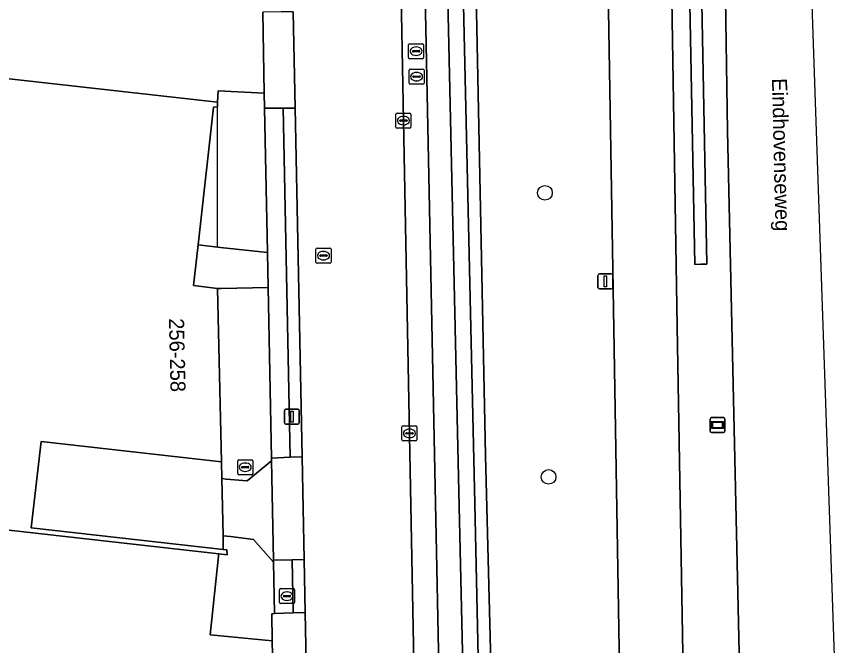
# Model space of a CAD drawing. Extents: x 161385 to 162589, y 388479 to 389756.
# Drawn here: x 162475.1 to 162530.5, y 388850.8 to 388892.6 of the extents above; entities that cross this region are included whole.
import ezdxf

# ---------------------------------------------------------------- set-up
doc = ezdxf.new("R2010")
doc.units = 0
for name, color, linetype in [('IMGEO_Berm_groen', 7, 'Continuous'), ('IMGEO_Boom', 7, 'Continuous'), ('IMGEO_Brandkraan', 7, 'Continuous'), ('IMGEO_Erf', 7, 'Continuous'), ('IMGEO_Fietspad_gesloten', 7, 'Continuous'), ('IMGEO_Groenvoorziening', 7, 'Continuous'), ('IMGEO_Haag', 7, 'Continuous'), ('IMGEO_Kolk', 7, 'Continuous'), ('IMGEO_Lichtmast', 7, 'Continuous'), ('IMGEO_Oever', 7, 'Continuous'), ('IMGEO_Openbare_ruimte_label', 7, 'Continuous'), ('IMGEO_Pand', 7, 'Continuous'), ('IMGEO_Pand_nummerreeks', 7, 'Continuous'), ('IMGEO_Pand_overbouw', 7, 'Continuous'), ('IMGEO_Rijbaan_lokaal_gesloten', 7, 'Continuous'), ('IMGEO_Rijbaan_regionaal_gesloten', 7, 'Continuous'), ('IMGEO_Rioolput', 7, 'Continuous'), ('IMGEO_Voetpad_open', 7, 'Continuous'), ('IMGEO_Waterloop', 7, 'Continuous'), ('IMGEO_Wegwijzer', 7, 'Continuous')]:
    doc.layers.add(name, color=color, linetype=linetype)

msp = doc.modelspace()

# ---------------------------------------------------------------- linework, layer by layer
at = {"layer": 'IMGEO_Berm_groen'}
for points in [[(162515.397, 389079.082), (162515.507, 389081.426), (162514.292, 389081.426), (162514.262, 389079.427), (162515.393, 389057.642), (162516.561, 389022.995), (162519.033, 388871.958), (162521.523, 388727.275)], [(162517.21, 388728.105), (162514.823, 388871.796), (162512.275, 389022.964), (162511.097, 389057.663), (162510.235, 389079.2)], [(162521.311, 388720.501), (162521.33, 388719.939), (162521.52, 388719.331), (162523.238, 388715.161), (162525.385, 388736.547), (162525.398, 388750), (162525.392, 388750.463), (162524.813, 388770.581), (162524.652, 388775.367), (162524.277, 388798.785), (162523.635, 388828.454), (162522.364, 388884.975), (162520.774, 388990.381)], [(162500.546, 388899.883), (162500.817, 388885.662), (162501.627, 388843.777), (162502.076, 388822.868), (162502.515, 388801.899), (162502.522, 388800.855), (162502.53, 388799.811), (162502.501, 388799.311), (162502.302, 388797.58), (162501.949, 388795.874), (162501.444, 388794.206), (162500.793, 388792.59), (162500, 388791.038), (162499.863, 388790.8), (162498.913, 388789.338), (162497.837, 388787.967), (162496.642, 388786.698)], [(162505.585, 388897.306), (162506.277, 388863.384), (162507.703, 388808.23), (162508.502, 388764.034), (162508.507, 388763.596), (162508.048, 388750), (162507.287, 388742.621), (162504.955, 388729.188), (162504.276, 388726.446), (162500, 388712.436), (162499.893, 388712.133), (162499.135, 388710.054), (162493.393, 388696.514), (162489.638, 388688.939), (162485.689, 388681.463), (162483.678, 388677.768)], [(162503.938, 388784.771), (162503.945, 388811.232), (162502.197, 388897.243)]]:
    msp.add_lwpolyline(points, dxfattribs=at)
for points in [[(162521, 388876.114), (162520.6, 388876.106), (162520.2, 388876.098), (162518.628, 388958.294), (162519.028, 388958.302), (162519.428, 388958.31)], [(162493.608, 388886.494), (162492.812, 388886.492), (162493.279, 388863.267), (162494.075, 388863.303)], [(162494.213, 388856.462), (162493.417, 388856.444), (162493.488, 388852.907), (162494.284, 388852.938)]]:
    msp.add_lwpolyline(points, close=True, dxfattribs=at)
at = {"layer": 'IMGEO_Boom'}
for centre in [(162510.232, 388880.857), (162510.475, 388861.96)]:
    msp.add_circle(centre, 0.489, dxfattribs=at)
at = {"layer": 'IMGEO_Brandkraan'}
for p, q in [((162492.571, 388853.599), (162492.571, 388854.451)), ((162492.646, 388854.525), (162493.498, 388854.525)), ((162493.059, 388854.305), (162493.084, 388854.305)), ((162493.572, 388854.451), (162493.572, 388853.599)), ((162492.83, 388854.019), (162492.83, 388854.031)), ((162493.268, 388853.982), (162492.87, 388853.982)), ((162492.873, 388854.068), (162493.271, 388854.068)), ((162493.082, 388853.745), (162493.057, 388853.745)), ((162493.314, 388854.031), (162493.314, 388854.019)), ((162493.498, 388853.525), (162492.646, 388853.525))]:
    msp.add_line(p, q, dxfattribs=at)
for points in [[(162492.571, 388853.599), (162492.571, 388854.451)], [(162492.646, 388854.525), (162493.498, 388854.525)], [(162493.572, 388854.451), (162493.572, 388853.599)], [(162493.498, 388853.525), (162492.646, 388853.525)]]:
    msp.add_lwpolyline(points, dxfattribs=at)
for centre, radius, start, end in [((162492.648, 388854.449), 0.0765, 91.552, 178.448), ((162492.648, 388854.449), 0.0765, 91.552, 178.448), ((162493.496, 388854.449), 0.0765, 1.552, 88.448), ((162493.496, 388854.449), 0.0765, 1.552, 88.448), ((162492.648, 388853.601), 0.0765, 181.552, 268.448), ((162492.648, 388853.601), 0.0765, 181.552, 268.448), ((162492.87, 388854.028), 0.0403, 85.8775, 175.7526), ((162492.867, 388854.018), 0.0366, 178.938, 274.7102), ((162493.271, 388854.025), 0.043, 264.8664, 352.4533), ((162493.275, 388854.03), 0.0386, 1.7309, 96.639), ((162493.496, 388853.601), 0.0765, 271.552, 358.448), ((162493.496, 388853.601), 0.0765, 271.552, 358.448)]:
    msp.add_arc(centre, radius, start, end, dxfattribs=at)
for centre, major_axis, ratio, start_param, end_param in [((162493.058, 388854.025), (-0.387, 0.002), 0.722429, 4.712389, 7.853982), ((162493.083, 388854.025), (-0.39, 0.002), 0.717154, 1.570796, 4.712389)]:
    msp.add_ellipse(centre, major_axis=major_axis, ratio=ratio, start_param=start_param, end_param=end_param, dxfattribs=at)
at = {"layer": 'IMGEO_Erf'}
msp.add_lwpolyline([(162423.214, 388797.141), (162434.552, 388795.859), (162435.263, 388802.18), (162436.753, 388802.017), (162439.735, 388801.682), (162439.879, 388801.637), (162440.168, 388805.317), (162445.286, 388850.441), (162482.306, 388846.26), (162482.466, 388837.077), (162482.487, 388836.004), (162487.823, 388836.098), (162489.492, 388836.131), (162492.433, 388836.158), (162492.098, 388851.061), (162487.953, 388851.459), (162488.523, 388856.678), (162488.541, 388856.845), (162437.609, 388862.581), (162440.94, 388892.207), (162488.443, 388886.892), (162488.497, 388887.644), (162491.565, 388887.495), (162491.458, 388892.887)], dxfattribs=at)
msp.add_lwpolyline([(162488.838, 388857.129), (162488.818, 388858.047), (162488.735, 388861.843), (162488.711, 388862.963), (162476.732, 388864.303), (162476.064, 388858.567)], close=True, dxfattribs=at)
at = {"layer": 'IMGEO_Fietspad_gesloten'}
for points in [[(162519.033, 388871.958), (162516.561, 389022.995), (162515.393, 389057.642), (162514.262, 389079.427), (162514.292, 389081.426), (162514.386, 389087.66), (162514.743, 389099.436), (162509.811, 389099.872), (162509.798, 389099.728), (162509.789, 389099.382), (162509.527, 389088.495), (162510.065, 389081.426), (162510.235, 389079.2), (162511.097, 389057.663), (162512.275, 389022.964), (162514.823, 388871.796), (162517.21, 388728.105)], [(162521.523, 388727.275), (162519.033, 388871.958)]]:
    msp.add_lwpolyline(points, dxfattribs=at)
at = {"layer": 'IMGEO_Groenvoorziening'}
for points in [[(162519.428, 388958.31), (162519.028, 388958.302), (162518.628, 388958.294), (162520.2, 388876.098), (162520.6, 388876.106), (162521, 388876.114)], [(162491.585, 388886.489), (162491.565, 388887.495), (162488.497, 388887.644), (162488.443, 388886.892), (162488.44, 388886.587), (162488.176, 388886.563), (162487.162, 388877.408), (162487.16, 388877.388), (162488.641, 388877.224), (162491.775, 388876.877)], [(162488.711, 388862.963), (162488.735, 388861.843), (162489.024, 388861.816), (162490.432, 388861.686), (162492.049, 388863.021), (162492.045, 388863.211), (162491.821, 388874.558), (162488.7, 388874.497), (162488.46, 388874.492)], [(162489.074, 388857.102), (162489.089, 388856.783), (162488.541, 388856.845), (162488.523, 388856.678), (162487.953, 388851.459), (162492.098, 388851.061), (162492.071, 388852.85), (162492.25, 388852.862), (162492.182, 388856.279), (162490.853, 388857.798), (162489.307, 388857.987), (162489.064, 388858.017), (162488.818, 388858.047), (162488.838, 388857.129)]]:
    msp.add_lwpolyline(points, close=True, dxfattribs=at)
at = {"layer": 'IMGEO_Haag'}
for points in [[(162519.428, 388958.31), (162519.028, 388958.302), (162518.628, 388958.294), (162520.2, 388876.098), (162520.6, 388876.106), (162521, 388876.114)], [(162488.711, 388862.963), (162488.735, 388861.843), (162489.024, 388861.816), (162490.432, 388861.686), (162492.049, 388863.021), (162492.045, 388863.211), (162491.821, 388874.558), (162488.7, 388874.497), (162488.46, 388874.492)]]:
    msp.add_lwpolyline(points, close=True, dxfattribs=at)
at = {"layer": 'IMGEO_Kolk'}
for p, q in [((162500.318, 388885.236), (162500.318, 388886.088)), ((162500.393, 388886.162), (162501.245, 388886.162)), ((162500.806, 388885.942), (162500.831, 388885.942)), ((162501.319, 388886.088), (162501.319, 388885.236)), ((162500.577, 388885.656), (162500.577, 388885.668)), ((162501.015, 388885.619), (162500.617, 388885.619)), ((162500.62, 388885.705), (162501.018, 388885.705)), ((162500.829, 388885.382), (162500.804, 388885.382)), ((162501.061, 388885.668), (162501.061, 388885.656)), ((162501.245, 388885.162), (162500.393, 388885.162)), ((162500.719, 388864.429), (162500.719, 388865.281)), ((162500.794, 388865.355), (162501.646, 388865.355)), ((162501.72, 388865.281), (162501.72, 388864.429)), ((162500.978, 388864.849), (162500.978, 388864.861)), ((162501.416, 388864.812), (162501.018, 388864.812)), ((162501.021, 388864.898), (162501.419, 388864.898)), ((162501.207, 388865.135), (162501.232, 388865.135)), ((162501.462, 388864.861), (162501.462, 388864.849)), ((162501.646, 388864.355), (162500.794, 388864.355)), ((162501.23, 388864.575), (162501.205, 388864.575))]:
    msp.add_line(p, q, dxfattribs=at)
for points in [[(162500.318, 388885.236), (162500.318, 388886.088)], [(162500.393, 388886.162), (162501.245, 388886.162)], [(162501.319, 388886.088), (162501.319, 388885.236)], [(162501.245, 388885.162), (162500.393, 388885.162)], [(162500.719, 388864.429), (162500.719, 388865.281)], [(162500.794, 388865.355), (162501.646, 388865.355)], [(162501.72, 388865.281), (162501.72, 388864.429)], [(162501.646, 388864.355), (162500.794, 388864.355)]]:
    msp.add_lwpolyline(points, dxfattribs=at)
for centre, radius, start, end in [((162500.395, 388886.086), 0.0765, 91.552, 178.448), ((162500.395, 388886.086), 0.0765, 91.552, 178.448), ((162501.243, 388886.086), 0.0765, 1.552, 88.448), ((162501.243, 388886.086), 0.0765, 1.552, 88.448), ((162500.395, 388885.238), 0.0765, 181.552, 268.448), ((162500.395, 388885.238), 0.0765, 181.552, 268.448), ((162500.617, 388885.665), 0.0403, 85.8775, 175.7526), ((162500.614, 388885.655), 0.0366, 178.938, 274.7102), ((162501.018, 388885.662), 0.043, 264.8664, 352.4533), ((162501.022, 388885.667), 0.0386, 1.7309, 96.639), ((162501.243, 388885.238), 0.0765, 271.552, 358.448), ((162501.243, 388885.238), 0.0765, 271.552, 358.448), ((162500.796, 388865.279), 0.0765, 91.552, 178.448), ((162500.796, 388865.279), 0.0765, 91.552, 178.448), ((162501.644, 388865.279), 0.0765, 1.552, 88.448), ((162501.644, 388865.279), 0.0765, 1.552, 88.448), ((162501.018, 388864.858), 0.0403, 85.8775, 175.7526), ((162501.015, 388864.848), 0.0366, 178.938, 274.7102), ((162501.419, 388864.855), 0.043, 264.8664, 352.4533), ((162501.423, 388864.86), 0.0386, 1.7309, 96.639), ((162500.796, 388864.431), 0.0765, 181.552, 268.448), ((162500.796, 388864.431), 0.0765, 181.552, 268.448), ((162501.644, 388864.431), 0.0765, 271.552, 358.448), ((162501.644, 388864.431), 0.0765, 271.552, 358.448)]:
    msp.add_arc(centre, radius, start, end, dxfattribs=at)
for centre, major_axis, ratio, start_param, end_param in [((162500.805, 388885.662), (-0.387, 0.002), 0.722429, 4.712389, 7.853982), ((162500.83, 388885.662), (-0.39, 0.002), 0.717154, 1.570796, 4.712389), ((162501.206, 388864.855), (-0.387, 0.002), 0.722429, 4.712389, 7.853982), ((162501.231, 388864.855), (-0.39, 0.002), 0.717154, 1.570796, 4.712389)]:
    msp.add_ellipse(centre, major_axis=major_axis, ratio=ratio, start_param=start_param, end_param=end_param, dxfattribs=at)
at = {"layer": 'IMGEO_Lichtmast'}
for p, q in [((162513.756, 388874.567), (162513.756, 388875.367)), ((162513.756, 388875.367), (162513.756, 388874.567)), ((162513.856, 388875.467), (162514.646, 388875.467)), ((162514.646, 388875.467), (162513.856, 388875.467)), ((162514.746, 388875.367), (162514.746, 388874.567)), ((162514.746, 388874.567), (162514.746, 388875.367)), ((162514.646, 388874.467), (162513.856, 388874.467)), ((162513.856, 388874.467), (162514.646, 388874.467)), ((162492.903, 388865.565), (162492.903, 388866.365)), ((162492.903, 388866.365), (162492.903, 388865.565)), ((162493.003, 388866.465), (162493.793, 388866.465)), ((162493.793, 388866.465), (162493.003, 388866.465)), ((162493.893, 388866.365), (162493.893, 388865.565)), ((162493.893, 388865.565), (162493.893, 388866.365)), ((162493.793, 388865.465), (162493.003, 388865.465)), ((162493.003, 388865.465), (162493.793, 388865.465))]:
    msp.add_line(p, q, dxfattribs=at)
for points in [[(162514.176, 388875.342), (162514.326, 388875.342), (162514.326, 388874.592), (162514.176, 388874.592), (162514.176, 388875.342)], [(162493.323, 388866.34), (162493.473, 388866.34), (162493.473, 388865.59), (162493.323, 388865.59), (162493.323, 388866.34)]]:
    msp.add_lwpolyline(points, dxfattribs=at)
for centre, start, end in [((162513.856, 388875.367), 90, 180), ((162513.856, 388875.367), 90, 180), ((162514.646, 388875.367), 0, 90), ((162514.646, 388875.367), 360, 90), ((162513.856, 388874.567), 180, 270), ((162513.856, 388874.567), 180, 270), ((162514.646, 388874.567), 270, 0), ((162514.646, 388874.567), 270, 0), ((162493.003, 388866.365), 90, 180), ((162493.003, 388866.365), 90, 180), ((162493.793, 388866.365), 0, 90), ((162493.793, 388866.365), 360, 90), ((162493.003, 388865.565), 180, 270), ((162493.003, 388865.565), 180, 270), ((162493.793, 388865.565), 270, 0), ((162493.793, 388865.565), 270, 0)]:
    msp.add_arc(centre, 0.1, start, end, dxfattribs=at)
at = {"layer": 'IMGEO_Oever'}
for points in [[(162500.804, 388721.953), (162503.142, 388731.482), (162504.195, 388736.481), (162505.954, 388751.52), (162506.349, 388762.359), (162506.053, 388775.359), (162505.188, 388821.013), (162504.94, 388841.621), (162504.505, 388860.971), (162503.038, 388926.396)], [(162504.093, 388925.58), (162505.561, 388860.155), (162505.995, 388840.805), (162506.244, 388820.196), (162507.105, 388775.346), (162507.405, 388761.542), (162507.01, 388750.703), (162505.251, 388735.665), (162504.198, 388730.666)], [(162502.197, 388897.243), (162503.945, 388811.232), (162503.938, 388784.771), (162504.239, 388778.441), (162504.847, 388765.637), (162504.058, 388750), (162501.776, 388732.254), (162500, 388725.157)], [(162504.955, 388729.188), (162507.287, 388742.621), (162508.048, 388750), (162508.507, 388763.596), (162508.502, 388764.034), (162507.703, 388808.23), (162506.277, 388863.384), (162505.585, 388897.306)]]:
    msp.add_lwpolyline(points, dxfattribs=at)
at = {"layer": 'IMGEO_Pand'}
msp.add_lwpolyline([(162487.16, 388877.388), (162487.162, 388877.408), (162488.176, 388886.563), (162488.44, 388886.587), (162488.443, 388886.892), (162440.94, 388892.207), (162437.609, 388862.581), (162488.541, 388856.845), (162489.089, 388856.783), (162489.074, 388857.102), (162488.838, 388857.129), (162476.064, 388858.567), (162476.732, 388864.303), (162488.711, 388862.963), (162488.46, 388874.492), (162486.86, 388874.682)], close=True, dxfattribs=at)
at = {"layer": 'IMGEO_Pand_overbouw'}
msp.add_lwpolyline([(162488.44, 388886.587), (162488.176, 388886.563), (162487.162, 388877.408), (162488.455, 388877.254)], close=True, dxfattribs=at)
at = {"layer": 'IMGEO_Rijbaan_lokaal_gesloten'}
msp.add_lwpolyline([(162493.479, 388892.905), (162493.608, 388886.494), (162494.075, 388863.303), (162494.213, 388856.462), (162494.284, 388852.938), (162494.665, 388834.017), (162495.332, 388800.906), (162502.522, 388800.855), (162502.515, 388801.899), (162502.076, 388822.868), (162501.627, 388843.777), (162500.817, 388885.662), (162500.546, 388899.883)], dxfattribs=at)
at = {"layer": 'IMGEO_Rijbaan_regionaal_gesloten'}
for points in [[(162522.824, 388687.961), (162524.933, 388693.486), (162530.479, 388820.962), (162524.33, 389000.689)], [(162520.774, 388990.381), (162522.364, 388884.975), (162523.635, 388828.454), (162524.277, 388798.785), (162524.652, 388775.367), (162524.813, 388770.581), (162525.392, 388750.463), (162525.398, 388750), (162525.385, 388736.547), (162525.238, 388728.029), (162525.099, 388721.415), (162524.726, 388716.57), (162524.5, 388713.353), (162524.479, 388713.183), (162523.543, 388705.46), (162523.188, 388703.163), (162523.396, 388703.055), (162520.22, 388691.521), (162519.529, 388689.152), (162522.824, 388687.961)]]:
    msp.add_lwpolyline(points, dxfattribs=at)
at = {"layer": 'IMGEO_Rioolput'}
for p, q in [((162501.161, 388889.853), (162501.161, 388890.705)), ((162501.236, 388890.779), (162502.088, 388890.779)), ((162502.162, 388890.705), (162502.162, 388889.853)), ((162501.42, 388890.273), (162501.42, 388890.285)), ((162501.858, 388890.236), (162501.46, 388890.236)), ((162501.463, 388890.322), (162501.861, 388890.322)), ((162501.649, 388890.559), (162501.674, 388890.559)), ((162501.904, 388890.285), (162501.904, 388890.273)), ((162502.088, 388889.779), (162501.236, 388889.779)), ((162501.672, 388889.999), (162501.647, 388889.999)), ((162501.267, 388889.085), (162502.119, 388889.085)), ((162501.192, 388888.159), (162501.192, 388889.011)), ((162501.451, 388888.579), (162501.451, 388888.591)), ((162501.889, 388888.542), (162501.491, 388888.542)), ((162501.494, 388888.628), (162501.892, 388888.628)), ((162501.68, 388888.865), (162501.705, 388888.865)), ((162501.935, 388888.591), (162501.935, 388888.579)), ((162502.193, 388889.011), (162502.193, 388888.159)), ((162502.119, 388888.085), (162501.267, 388888.085)), ((162501.703, 388888.305), (162501.678, 388888.305)), ((162495.001, 388876.252), (162495.001, 388877.104)), ((162495.076, 388877.178), (162495.928, 388877.178)), ((162495.489, 388876.958), (162495.514, 388876.958)), ((162496.002, 388877.104), (162496.002, 388876.252)), ((162495.26, 388876.672), (162495.26, 388876.684)), ((162495.698, 388876.635), (162495.3, 388876.635)), ((162495.303, 388876.721), (162495.701, 388876.721)), ((162495.512, 388876.398), (162495.487, 388876.398)), ((162495.744, 388876.684), (162495.744, 388876.672)), ((162495.928, 388876.178), (162495.076, 388876.178)), ((162489.794, 388862.175), (162489.794, 388863.027)), ((162489.869, 388863.101), (162490.721, 388863.101)), ((162490.795, 388863.027), (162490.795, 388862.175)), ((162490.053, 388862.595), (162490.053, 388862.607)), ((162490.491, 388862.558), (162490.093, 388862.558)), ((162490.096, 388862.644), (162490.494, 388862.644)), ((162490.282, 388862.881), (162490.307, 388862.881)), ((162490.537, 388862.607), (162490.537, 388862.595)), ((162490.721, 388862.101), (162489.869, 388862.101)), ((162490.305, 388862.321), (162490.28, 388862.321))]:
    msp.add_line(p, q, dxfattribs=at)
for points in [[(162501.161, 388889.853), (162501.161, 388890.705)], [(162501.236, 388890.779), (162502.088, 388890.779)], [(162502.162, 388890.705), (162502.162, 388889.853)], [(162502.088, 388889.779), (162501.236, 388889.779)], [(162501.267, 388889.085), (162502.119, 388889.085)], [(162501.192, 388888.159), (162501.192, 388889.011)], [(162502.193, 388889.011), (162502.193, 388888.159)], [(162502.119, 388888.085), (162501.267, 388888.085)], [(162495.001, 388876.252), (162495.001, 388877.104)], [(162495.076, 388877.178), (162495.928, 388877.178)], [(162496.002, 388877.104), (162496.002, 388876.252)], [(162495.928, 388876.178), (162495.076, 388876.178)], [(162489.794, 388862.175), (162489.794, 388863.027)], [(162489.869, 388863.101), (162490.721, 388863.101)], [(162490.795, 388863.027), (162490.795, 388862.175)], [(162490.721, 388862.101), (162489.869, 388862.101)]]:
    msp.add_lwpolyline(points, dxfattribs=at)
for centre, radius, start, end in [((162501.238, 388890.703), 0.0765, 91.552, 178.448), ((162501.238, 388890.703), 0.0765, 91.552, 178.448), ((162502.086, 388890.703), 0.0765, 1.552, 88.448), ((162502.086, 388890.703), 0.0765, 1.552, 88.448), ((162501.46, 388890.282), 0.0403, 85.8775, 175.7526), ((162501.457, 388890.272), 0.0366, 178.938, 274.7102), ((162501.861, 388890.279), 0.043, 264.8664, 352.4533), ((162501.865, 388890.284), 0.0386, 1.7309, 96.639), ((162501.238, 388889.855), 0.0765, 181.552, 268.448), ((162501.238, 388889.855), 0.0765, 181.552, 268.448), ((162502.086, 388889.855), 0.0765, 271.552, 358.448), ((162502.086, 388889.855), 0.0765, 271.552, 358.448), ((162501.269, 388889.009), 0.0765, 91.552, 178.448), ((162501.269, 388889.009), 0.0765, 91.552, 178.448), ((162502.117, 388889.009), 0.0765, 1.552, 88.448), ((162502.117, 388889.009), 0.0765, 1.552, 88.448), ((162501.491, 388888.588), 0.0403, 85.8775, 175.7526), ((162501.488, 388888.578), 0.0366, 178.938, 274.7102), ((162501.892, 388888.585), 0.043, 264.8664, 352.4533), ((162501.896, 388888.59), 0.0386, 1.7309, 96.639), ((162501.269, 388888.161), 0.0765, 181.552, 268.448), ((162501.269, 388888.161), 0.0765, 181.552, 268.448), ((162502.117, 388888.161), 0.0765, 271.552, 358.448), ((162502.117, 388888.161), 0.0765, 271.552, 358.448), ((162495.078, 388877.102), 0.0765, 91.552, 178.448), ((162495.078, 388877.102), 0.0765, 91.552, 178.448), ((162495.926, 388877.102), 0.0765, 1.552, 88.448), ((162495.926, 388877.102), 0.0765, 1.552, 88.448), ((162495.3, 388876.681), 0.0403, 85.8775, 175.7526), ((162495.297, 388876.671), 0.0366, 178.938, 274.7102), ((162495.701, 388876.678), 0.043, 264.8664, 352.4533), ((162495.705, 388876.683), 0.0386, 1.7309, 96.639), ((162495.078, 388876.254), 0.0765, 181.552, 268.448), ((162495.078, 388876.254), 0.0765, 181.552, 268.448), ((162495.926, 388876.254), 0.0765, 271.552, 358.448), ((162495.926, 388876.254), 0.0765, 271.552, 358.448), ((162489.871, 388863.025), 0.0765, 91.552, 178.448), ((162489.871, 388863.025), 0.0765, 91.552, 178.448), ((162490.719, 388863.025), 0.0765, 1.552, 88.448), ((162490.719, 388863.025), 0.0765, 1.552, 88.448), ((162490.093, 388862.604), 0.0403, 85.8775, 175.7526), ((162490.09, 388862.594), 0.0366, 178.938, 274.7102), ((162490.494, 388862.601), 0.043, 264.8664, 352.4533), ((162490.498, 388862.606), 0.0386, 1.7309, 96.639), ((162489.871, 388862.177), 0.0765, 181.552, 268.448), ((162489.871, 388862.177), 0.0765, 181.552, 268.448), ((162490.719, 388862.177), 0.0765, 271.552, 358.448), ((162490.719, 388862.177), 0.0765, 271.552, 358.448)]:
    msp.add_arc(centre, radius, start, end, dxfattribs=at)
for centre, major_axis, ratio, start_param, end_param in [((162501.648, 388890.279), (-0.387, 0.002), 0.722429, 4.712389, 7.853982), ((162501.673, 388890.279), (-0.39, 0.002), 0.717154, 1.570796, 4.712389), ((162501.679, 388888.585), (-0.387, 0.002), 0.722429, 4.712389, 7.853982), ((162501.704, 388888.585), (-0.39, 0.002), 0.717154, 1.570796, 4.712389), ((162495.488, 388876.678), (-0.387, 0.002), 0.722429, 4.712389, 7.853982), ((162495.513, 388876.678), (-0.39, 0.002), 0.717154, 1.570796, 4.712389), ((162490.281, 388862.601), (-0.387, 0.002), 0.722429, 4.712389, 7.853982), ((162490.306, 388862.601), (-0.39, 0.002), 0.717154, 1.570796, 4.712389)]:
    msp.add_ellipse(centre, major_axis=major_axis, ratio=ratio, start_param=start_param, end_param=end_param, dxfattribs=at)
at = {"layer": 'IMGEO_Voetpad_open'}
for points in [[(162491.585, 388886.489), (162492.812, 388886.492), (162493.608, 388886.494), (162493.479, 388892.905), (162492.683, 388892.898), (162491.458, 388892.887), (162491.565, 388887.495)], [(162491.821, 388874.558), (162492.045, 388863.211), (162493.279, 388863.267), (162492.812, 388886.492), (162491.585, 388886.489), (162491.775, 388876.877)], [(162488.7, 388874.497), (162491.821, 388874.558), (162491.775, 388876.877), (162488.641, 388877.224), (162487.16, 388877.388), (162486.86, 388874.682), (162488.46, 388874.492)], [(162489.064, 388858.017), (162489.307, 388857.987), (162490.853, 388857.798), (162492.182, 388856.279), (162492.18, 388856.415), (162492.049, 388863.021), (162490.432, 388861.686), (162489.024, 388861.816), (162488.735, 388861.843), (162488.818, 388858.047)], [(162494.213, 388856.462), (162494.075, 388863.303), (162493.279, 388863.267), (162492.045, 388863.211), (162492.049, 388863.021), (162492.18, 388856.415), (162493.417, 388856.444)], [(162493.417, 388856.444), (162492.18, 388856.415), (162492.182, 388856.279), (162492.25, 388852.862), (162493.488, 388852.907)], [(162493.488, 388852.907), (162492.25, 388852.862), (162492.071, 388852.85), (162492.098, 388851.061), (162492.433, 388836.158), (162492.489, 388834.022), (162492.653, 388834.028), (162493.855, 388834.039), (162494.665, 388834.017), (162494.284, 388852.938)]]:
    msp.add_lwpolyline(points, close=True, dxfattribs=at)
at = {"layer": 'IMGEO_Waterloop'}
for points in [[(162503.038, 388926.396), (162504.505, 388860.971), (162504.94, 388841.621), (162505.188, 388821.013), (162506.053, 388775.359), (162506.349, 388762.359), (162505.954, 388751.52), (162504.195, 388736.481), (162503.142, 388731.482), (162500.804, 388721.953)], [(162504.198, 388730.666), (162505.251, 388735.665), (162507.01, 388750.703), (162507.405, 388761.542), (162507.105, 388775.346), (162506.244, 388820.196), (162505.995, 388840.805), (162505.561, 388860.155), (162504.093, 388925.58)]]:
    msp.add_lwpolyline(points, dxfattribs=at)
at = {"layer": 'IMGEO_Wegwijzer'}
for p, q in [((162521.216, 388865.003), (162521.216, 388865.803)), ((162521.216, 388865.803), (162521.216, 388865.003)), ((162521.316, 388865.903), (162522.106, 388865.903)), ((162522.106, 388865.903), (162521.316, 388865.903)), ((162522.206, 388865.803), (162522.206, 388865.003)), ((162522.206, 388865.003), (162522.206, 388865.803)), ((162522.106, 388864.903), (162521.316, 388864.903)), ((162521.316, 388864.903), (162522.106, 388864.903))]:
    msp.add_line(p, q, dxfattribs=at)
for points in [[(162521.317, 388865.635), (162522.105, 388865.635), (162522.105, 388865.171), (162521.317, 388865.171), (162521.317, 388865.635)], [(162521.382, 388865.57), (162521.382, 388865.236), (162522.04, 388865.236), (162522.04, 388865.57), (162521.382, 388865.57)]]:
    msp.add_lwpolyline(points, dxfattribs=at)
for centre, start, end in [((162521.316, 388865.803), 90, 180), ((162521.316, 388865.803), 90, 180), ((162522.106, 388865.803), 0, 90), ((162522.106, 388865.803), 360, 90), ((162521.316, 388865.003), 180, 270), ((162521.316, 388865.003), 180, 270), ((162522.106, 388865.003), 270, 0), ((162522.106, 388865.003), 270, 0)]:
    msp.add_arc(centre, 0.1, start, end, dxfattribs=at)

# ---------------------------------------------------------------- texts
at = {"layer": 'IMGEO_Openbare_ruimte_label'}
msp.add_text('Eindhovenseweg', height=1, rotation=271.3176, dxfattribs=at).set_placement((162525.332, 388888.47))
at = {"layer": 'IMGEO_Pand_nummerreeks'}
msp.add_text('256-258', height=1, rotation=271.2488, dxfattribs=at).set_placement((162485.222, 388872.502))

doc.saveas('drawing.dxf')
